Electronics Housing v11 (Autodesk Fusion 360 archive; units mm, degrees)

design "Electronics Housing" references "OLED", "LRS-35-12", "PBC"
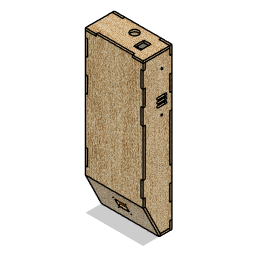
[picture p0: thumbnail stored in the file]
named bodies: "Floor", "front", "Back", "Top", "Display Pannel", "Left Side", "Right side"

design "PBC"
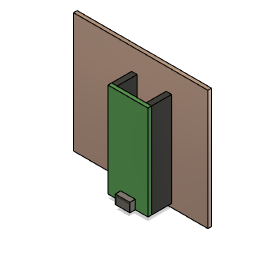
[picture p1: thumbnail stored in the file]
sketch "Sketch1" plane through (0, 0, 0) normal (0, 0, 1) x axis (1, 0, 0)
  line L1 (74, 0) -> (0, 0)
  line L2 (74, 66) -> (74, 0)
  line L3 (0, 66) -> (74, 66)
  line L4 (0, 0) -> (0, 66)
  point P1 (0, 0)
  point P2 (0, 0)
  point P3 (74, 0)
  point P4 (74, 66)
  point P5 (0, 66)
  horizontal L1
  vertical L2
  horizontal L3
  vertical L4
  coincident P1 P2
  dimension "d1" distance P3 P4 = 66
  dimension "d2" distance P4 P5 = 74
extrude "Extrude1" new body sketch "Sketch1" along normal blind 2
sketch "Sketch2" plane through (0, 0, 2) normal (0, 0, 1) x axis (1, 0, 0)
  line L1 (0, 0) -> (0, 66)
  line L2 (74, 0) -> (0, 0)
  line L3 (74, 66) -> (74, 0)
  line L4 (0, 66) -> (74, 66)
  line L5 (54, 54) -> (51, 54)
  line L6 (54, 2) -> (54, 54)
  line L7 (51, 2) -> (54, 2)
  line L8 (51, 54) -> (51, 2)
  line L9 (35, 54) -> (32, 54)
  line L10 (35, 2) -> (35, 54)
  line L11 (32, 2) -> (35, 2)
  line L12 (32, 54) -> (32, 2)
  point P10 (32, 54)
  point P11 (35, 54)
  point P12 (35, 2)
  point P7 (54, 54)
  point P8 (54, 2)
  horizontal L5
  vertical L6
  horizontal L7
  vertical L8
  horizontal L9
  vertical L10
  horizontal L11
  vertical L12
  dimension "d5" distance L3 L6 = 20
  dimension "d6" distance L6 L8 = 3
  dimension "d7" distance P10 P11 = 3
  dimension "d8" distance L6 L12 = 22
  dimension "d9" distance P10 P12 = 52
  dimension "d10" distance P7 P8 = 52
  dimension "d11" distance L4 P10 = 12
  dimension "d12" distance L4 L5 = 12
extrude "Extrude2" new body sketch "Sketch2" profile of L5 L6 L7 L8 L9 L10 L11 L12 along normal blind 11
work_plane "WorkPlane1" AlongDistance 0
sketch "Sketch3" plane through (0, 0, 13) normal (0, 0, 1) x axis (1, 0, 0)
  line L1 (32, 2) -> (32, 54)
  line L2 (54, 54) -> (54, 2)
  line L3 (54, 54) -> (32, 54)
  line L4 (54, 2) -> (54, 54)
  line L5 (32, 2) -> (54, 2)
  line L6 (32, 54) -> (32, 2)
  point P4 (54, 2)
  point P8 (54, 2)
  point P2 (32, 54)
  point P6 (32, 54)
  horizontal L3
  vertical L4
  horizontal L5
  vertical L6
  coincident P4 P8
  coincident P2 P6
extrude "Extrude3" new body sketch "Sketch3" along normal blind 2
sketch "Sketch4" plane through (0, 0, 15) normal (0, 0, 1) x axis (1, 0, 0)
  line L1 (54, 2) -> (32, 2)
  line L2 (54, 54) -> (54, 2)
  line L3 (32, 54) -> (54, 54)
  line L4 (32, 2) -> (32, 54)
  line L5 (43, 54) -> (43, 2)
  line L6 (47, 2) -> (39, 2)
  line L7 (47, 7) -> (47, 2)
  line L8 (39, 7) -> (47, 7)
  line L9 (39, 2) -> (39, 7)
  point P6 (43, 2)
  point P7 (43, 54)
  point P8 (39, 2)
  point P11 (39, 7)
  point P10 (47, 7)
  midpoint L1 P6
  midpoint L3 P7
  horizontal L6
  vertical L7
  horizontal L8
  vertical L9
  coincident L1 P8
  symmetric L5 L7 L9
  dimension "d18" distance P8 P11 = 5
  dimension "d19" distance P10 P11 = 8
extrude "Extrude4" new body sketch "Sketch4" profile of L1 L5 L6 L7 L8 L9 along normal blind 3
sketch "Sketch5" plane through (0, 2, 0) normal (0, -1, 0) x axis (1, 0, 0)
  line L1 (47, 15) -> (39, 15)
  line L2 (47, 18) -> (47, 15)
  line L3 (39, 18) -> (47, 18)
  line L4 (39, 15) -> (39, 18)
  line L5 (45.5, 17.2106) -> (40.5, 17.2106)
  line L6 (45.5, 16.6106) -> (45.5, 17.2106)
  line L7 (40.5, 16.6106) -> (45.5, 16.6106)
  line L8 (40.5, 17.2106) -> (40.5, 16.6106)
  line L9 (43, 15) -> (43, 18)
  line L10 (46.5833, 17.6974) -> (39.4167, 17.6974)
  line L11 (46.5833, 15.3264) -> (46.5833, 17.6974)
  line L12 (39.4167, 15.3264) -> (46.5833, 15.3264)
  line L13 (39.4167, 17.6974) -> (39.4167, 15.3264)
  point P10 (43, 18)
  point P11 (43, 15)
  point P6 (40.5, 17.2106)
  point P7 (45.5, 17.2106)
  horizontal L5
  vertical L6
  horizontal L7
  vertical L8
  midpoint L3 P10
  midpoint L1 P11
  symmetric L6 L8 L9
  horizontal L10
  vertical L11
  horizontal L12
  vertical L13
  symmetric L9 L11 L13
  dimension "d22" distance L5 L7 = 0.6
  dimension "d23" distance P6 P7 = 5
  dimension "d24" distance L1 L7 = 1.6106
  dimension "d25" distance L1 L12 = 0.3264
  dimension "d26" distance L4 L13 = 0.4167
  dimension "d27" distance L10 L12 = 2.371
extrude "Extrude5" cut sketch "Sketch5" profile of L5 L6 L7 L8 L9 L10 L11 L12 L13 against normal blind 4
sketch "Sketch6" plane through (0, 0, 0) normal (0, 1, 0) x axis (1, 0, 0)

design "OLED"
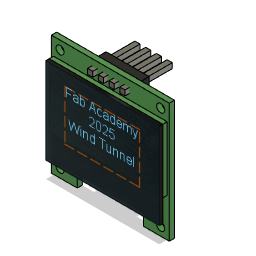
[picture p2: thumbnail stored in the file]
sketch "Sketch1" plane through (0, 0, 0) normal (0, 0, 1) x axis (1, 0, 0)
  line L1 (-13.7, 13.9) -> (13.7, 13.9)
  line L2 (-13.7, -13.9) -> (-13.7, 13.9)
  line L3 (13.7, 13.9) -> (13.7, -13.9)
  line L4 (-13.7, -13.9) -> (13.7, 13.9)
  line L5 (13.7, -13.9) -> (-13.7, 13.9)
  line L6 (13.7, 0) -> (-13.7, 0)
  line L7 (-7.7, -11.9) -> (-7.7, -13.9)
  line L8 (6.7, -10.9) -> (-6.7, -10.9)
  line L9 (7.7, -13.9) -> (7.7, -11.9)
  line L10 (-7.7, -13.9) -> (-13.7, -13.9)
  line L11 (13.7, -13.9) -> (7.7, -13.9)
  circle C1 centre (-11.7, 11.9) radius 0.95
  circle C2 centre (11.7, 11.9) radius 0.95
  circle C3 centre (-11.7, -11.9) radius 0.95
  circle C4 centre (11.7, -11.9) radius 0.95
  arc A1 centre (-6.7, -11.9) radius 1 clockwise from (-7.7, -11.9) to (-6.7, -10.9)
  arc A2 centre (6.7, -11.9) radius 1 clockwise from (6.7, -10.9) to (7.7, -11.9)
  point P6 (0, 0)
  point P1 (0, 0)
  point P9 (-13.7, 0)
  point P10 (13.7, 0)
  point P14 (7.7, -13.9)
  point P3 (-13.7, 13.9)
  point P4 (-13.7, -13.9)
  point P2 (13.7, 13.9)
  point P7 (-11.7, 11.9)
  point P8 (11.7, 11.9)
  horizontal L1
  perpendicular L1 L2
  parallel L1 L10
  parallel L2 L3
  coincident L4 P6
  coincident L5 P6
  coincident P1 P6
  midpoint L2 P9
  midpoint L3 P10
  symmetric C1 L6 C3
  symmetric C2 L6 C4
  perpendicular L7 L10
  perpendicular L7 L8
  coincident P14 L10
  perpendicular L9 L10
  tangent L7 A1
  tangent L8 A1
  tangent L8 A2
  tangent L9 A2
  equal A1 A2
  collinear L10 L11
  dimension "d1" distance P3 P4 = 27.8
  dimension "d2" distance P2 P3 = 27.4
  dimension "d3" diameter C1 = 1.9
  dimension "d4" distance L1 P7 = 2
  dimension "d5" distance L2 P7 = 2
  dimension "d6" diameter C2 = 1.9
  dimension "d7" distance L1 P8 = 2
  dimension "d8" distance L3 P8 = 2
  dimension "d17" radius A1 = 1
  dimension "d18" distance L2 L7 = 6
  dimension "d19" distance L3 L9 = 6
  dimension "d20" distance L8 L10 = 3
extrude "Extrude1" new body sketch "Sketch1" profile of L1 L2 L11 L3 C1 C2 C3 C4 along normal blind 1.2
sketch "Sketch2" plane through (0, 0, 1.2) normal (0, 0, 1) x axis (1, 0, 0)
  line L1 (13.7, 13.9) -> (13.7, -13.9)
  line L2 (-13.7, 13.9) -> (13.7, 13.9)
  line L3 (-13.7, -13.9) -> (-13.7, 13.9)
  line L4 (13.7, -13.9) -> (7.7, -13.9)
  line L5 (13.2, 9.9) -> (-13.2, 9.9)
  line L6 (13.2, -4.9) -> (13.2, 9.9)
  line L7 (-13.2, -4.9) -> (13.2, -4.9)
  line L8 (-13.2, 9.9) -> (-13.2, -4.9)
  line L9 (7.7, -13.9) -> (7.7, -11.9)
  line L10 (-7.7, -13.9) -> (-13.7, -13.9)
  line L11 (-7.7, -11.9) -> (-7.7, -13.9)
  line L12 (6.7, -10.9) -> (-6.7, -10.9)
  circle C1 centre (11.7, -11.9) radius 0.95
  circle C2 centre (-11.7, -11.9) radius 0.95
  circle C3 centre (-11.7, 11.9) radius 0.95
  circle C4 centre (11.7, 11.9) radius 0.95
  arc A1 centre (-6.7, -11.9) radius 1 clockwise from (-7.7, -11.9) to (-6.7, -10.9)
  arc A2 centre (6.7, -11.9) radius 1 clockwise from (6.7, -10.9) to (7.7, -11.9)
  horizontal L5
  vertical L6
  horizontal L7
  vertical L8
  dimension "d11" distance L2 L5 = 4
  dimension "d12" distance L4 L7 = 9
  dimension "d13" distance L3 L8 = 0.5
  dimension "d14" distance L1 L6 = 0.5
extrude "Extrude2" add sketch "Sketch2" + "Sketch3" profile of S1:L5 S1:L6 S1:L7 S1:L8 blind 1
sketch "Sketch3" plane through (0, 0, 2.2) normal (0, 0, 1) x axis (1, 0, 0)
  line L1 (13.2, -4.9) -> (-13.2, -4.9)
  line L2 (13.2, 9.9) -> (13.2, -4.9)
  line L3 (-13.2, 9.9) -> (13.2, 9.9)
  line L4 (-13.2, -4.9) -> (-13.2, 9.9)
  line L5 (13.2, 9.9) -> (-13.2, 9.9)
  line L6 (13.2, -10.1) -> (13.2, 9.9)
  line L7 (-13.2, -10.1) -> (13.2, -10.1)
  line L8 (-13.2, 9.9) -> (-13.2, -10.1)
  point P5 (-13.2, 9.9)
  point P6 (-13.2, 9.9)
  point P7 (13.2, 9.9)
  point P8 (13.2, -10.1)
  horizontal L5
  vertical L6
  horizontal L7
  vertical L8
  coincident P5 P6
  dimension "d21" distance P7 P8 = 20
  dimension "d22" distance L6 L8 = 26.4
extrude "Extrude3" new body sketch "Sketch3" along normal blind 0.8
sketch "Sketch4" plane through (0, 0, 0) normal (0, 0, -1) x axis (-1, 0, 0)
  line L1 (-7.7, -11.9) -> (-7.7, -13.9)
  line L2 (6.7, -10.9) -> (-6.7, -10.9)
  line L3 (7.7, -13.9) -> (7.7, -11.9)
  line L4 (13.7, -13.9) -> (7.7, -13.9)
  line L5 (13.7, 13.9) -> (13.7, -13.9)
  line L6 (-13.7, 13.9) -> (13.7, 13.9)
  line L7 (-13.7, -13.9) -> (-13.7, 13.9)
  line L8 (-7.7, -13.9) -> (-13.7, -13.9)
  line L9 (5, 12.9) -> (-5, 12.9)
  line L10 (5, 10.7) -> (5, 12.9)
  line L11 (-5, 10.7) -> (5, 10.7)
  line L12 (-5, 12.9) -> (-5, 10.7)
  line L13 (0, -10.9) -> (0, 13.9)
  circle C1 centre (-11.7, -11.9) radius 0.95
  circle C2 centre (-11.7, 11.9) radius 0.95
  circle C3 centre (11.7, -11.9) radius 0.95
  circle C4 centre (11.7, 11.9) radius 0.95
  arc A1 centre (-6.7, -11.9) radius 1 clockwise from (-7.7, -11.9) to (-6.7, -10.9)
  arc A2 centre (6.7, -11.9) radius 1 clockwise from (6.7, -10.9) to (7.7, -11.9)
  point P22 (0, 13.9)
  point P23 (0, -10.9)
  point P20 (5, 10.7)
  point P21 (-5, 10.7)
  point P18 (-5, 12.9)
  horizontal L9
  vertical L10
  horizontal L11
  vertical L12
  midpoint L6 P22
  midpoint L2 P23
  dimension "d25" distance P20 P21 = 10
  dimension "d26" distance L6 L9 = 1
  dimension "d27" distance P18 P21 = 2.2
extrude "Extrude4" new body sketch "Sketch4" profile of L9 L10 L11 L12 along normal blind 2.8
sketch "Sketch5" plane through (0, 0, -2.8) normal (0, 0, -1) x axis (-1, 0, 0)
  line L1 (5, 10.7) -> (-5, 10.7)
  line L2 (5, 12.9) -> (5, 10.7)
  line L3 (-5, 12.9) -> (5, 12.9)
  line L4 (-5, 10.7) -> (-5, 12.9)
  line L5 (5, 11.8) -> (-5, 11.8)
  line L6 (-3.2, 12.4) -> (-4.4, 12.4)
  line L7 (-3.2, 11.2) -> (-3.2, 12.4)
  line L8 (-4.4, 11.2) -> (-3.2, 11.2)
  line L9 (-4.4, 12.4) -> (-4.4, 11.2)
  line L10 (-0.7, 11.2) -> (-0.7, 12.4)
  line L11 (-0.7, 12.4) -> (-1.9, 12.4)
  line L12 (-1.9, 12.4) -> (-1.9, 11.2)
  line L13 (-1.9, 11.2) -> (-0.7, 11.2)
  line L14 (1.8, 11.2) -> (1.8, 12.4)
  line L15 (1.8, 12.4) -> (0.6, 12.4)
  line L16 (0.6, 12.4) -> (0.6, 11.2)
  line L17 (0.6, 11.2) -> (1.8, 11.2)
  line L18 (4.3, 11.2) -> (4.3, 12.4)
  line L19 (4.3, 12.4) -> (3.1, 12.4)
  line L20 (3.1, 12.4) -> (3.1, 11.2)
  line L21 (3.1, 11.2) -> (4.3, 11.2)
  point P6 (-5, 11.8)
  point P7 (5, 11.8)
  point P8 (-4.4, 12.4)
  point P9 (-3.2, 12.4)
  point P10 (-3.2, 11.2)
  midpoint L4 P6
  midpoint L2 P7
  horizontal L6
  vertical L7
  horizontal L8
  vertical L9
  symmetric L5 L6 L8
  dimension "d30" distance P8 P9 = 1.2
  dimension "d31" distance P9 P10 = 1.2
  dimension "d32" distance L4 L9 = 0.6
  dimension "d35" R-Pattern1-uDistance = 7.5
  dimension "d36" R-Pattern1-vDistance = 0
extrude "Extrude5" new body sketch "Sketch5" profile of L6 L7 L8 L9 L10 L11 L12 L13 L14 L15 L16 L17 L18 L19 L20 L21 along normal blind 6 and against normal blind 5
sketch "Sketch6" plane through (0, 0, 3) normal (0, 0, 1) x axis (1, 0, 0)
  dimension "d41" = 2

design "LRS-35-12"
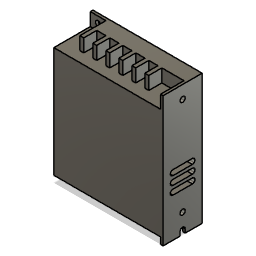
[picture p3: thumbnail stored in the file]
sketch "Sketch1" plane through (0, 0, 0) normal (0, 0, 1) x axis (1, 0, 0)
  line L1 (2, 0) -> (0, 0)
  line L2 (2, 100) -> (2, 0)
  line L3 (0, 100) -> (2, 100)
  line L4 (0, 0) -> (0, 100)
  point P1 (0, 0)
  point P2 (0, 0)
  point P3 (2, 0)
  point P5 (0, 100)
  horizontal L1
  vertical L2
  horizontal L3
  vertical L4
  coincident P1 P2
  dimension "d1" distance P2 P3 = 2
  dimension "d2" distance P2 P5 = 100
extrude "Extrude1" new body sketch "Sketch1" along normal blind 30
sketch "Sketch2" plane through (0, 0, 0) normal (0, 0, 1) x axis (1, 0, 0)
  line L1 (-82, 0) -> (0, 0)
  line L2 (-82, 100) -> (-82, 0)
  line L3 (0, 100) -> (-82, 100)
  line L4 (0, 0) -> (0, 100)
  point P1 (0, 0)
  point P2 (0, 0)
  point P5 (0, 100)
  point P3 (-82, 0)
  horizontal L1
  vertical L2
  horizontal L3
  vertical L4
  coincident P1 P2
  dimension "d5" distance P2 P5 = 100
  dimension "d6" distance P2 P3 = 82
extrude "Extrude2" add sketch "Sketch2" along normal blind 2
sketch "Sketch3" plane through (0, 0, 2) normal (0, 0, 1) x axis (1, 0, 0)
  line L1 (-82, 100) -> (0, 100)
  line L2 (-82, 0) -> (-82, 100)
  line L3 (0, 0) -> (-82, 0)
  line L4 (0, 100) -> (0, 0)
  line L5 (-82, 5) -> (0, 5)
  line L6 (-82, 90) -> (-82, 5)
  line L7 (0, 90) -> (-82, 90)
  line L8 (0, 5) -> (0, 90)
  point P6 (0, 5)
  point P8 (-82, 90)
  horizontal L5
  vertical L6
  horizontal L7
  vertical L8
  coincident L4 P6
  coincident L2 P8
  dimension "d9" distance L3 L5 = 5
  dimension "d10" distance L1 L7 = 10
extrude "Extrude3" add sketch "Sketch3" profile of L2 L4 L5 L6 L7 L8 along normal blind 28
sketch "Sketch4" plane through (0, 0, 2) normal (0, 0, 1) x axis (1, 0, 0)
  line L1 (0, 90) -> (-82, 90)
  line L2 (0, 100) -> (0, 90)
  line L3 (-82, 100) -> (0, 100)
  line L4 (-82, 90) -> (-82, 100)
  line L5 (0, 100) -> (-70, 100)
  line L6 (0, 90) -> (0, 100)
  line L7 (-70, 90) -> (0, 90)
  line L8 (-70, 100) -> (-70, 90)
  point P3 (0, 90)
  point P8 (0, 90)
  point P6 (-70, 100)
  point P7 (0, 100)
  horizontal L5
  vertical L6
  horizontal L7
  vertical L8
  coincident P3 P8
  coincident L3 P6
  dimension "d13" distance P6 P7 = 70
extrude "Extrude4" add sketch "Sketch4" profile of L1 L2 L3 L5 L6 L7 L8 along normal blind 20
sketch "Sketch5" plane through (0, 0, 22) normal (0, 0, 1) x axis (1, 0, 0)
  line L1 (0, 90) -> (-70, 90)
  line L2 (0, 100) -> (0, 90)
  line L3 (-70, 100) -> (0, 100)
  line L4 (-70, 90) -> (-70, 100)
  line L5 (-60, 100) -> (-67, 100)
  line L6 (-60, 90) -> (-60, 100)
  line L7 (-67, 90) -> (-60, 90)
  line L8 (-67, 100) -> (-67, 90)
  line L9 (-17, 103.9191) -> (-17, 90)
  line L10 (-57, 100) -> (-57, 90)
  line L11 (-50, 100) -> (-57, 100)
  line L12 (-50, 90) -> (-50, 100)
  line L13 (-57, 90) -> (-50, 90)
  line L14 (-47, 100) -> (-47, 90)
  line L15 (-40, 100) -> (-47, 100)
  line L16 (-40, 90) -> (-40, 100)
  line L17 (-47, 90) -> (-40, 90)
  line L18 (-37, 100) -> (-37, 90)
  line L19 (-30, 100) -> (-37, 100)
  line L20 (-30, 90) -> (-30, 100)
  line L21 (-37, 90) -> (-30, 90)
  line L22 (-27, 100) -> (-27, 90)
  line L23 (-20, 100) -> (-27, 100)
  line L24 (-20, 90) -> (-20, 100)
  line L25 (-27, 90) -> (-20, 90)
  line L26 (0, 100) -> (-17, 100)
  line L27 (0, 90) -> (0, 100)
  line L28 (-17, 90) -> (0, 90)
  line L29 (-17, 100) -> (-17, 90)
  point P8 (-60, 90)
  point P6 (-67, 100)
  point P10 (-17, 90)
  point P3 (0, 90)
  point P30 (0, 90)
  point P28 (-17, 100)
  point P7 (-60, 100)
  horizontal L5
  vertical L6
  horizontal L7
  vertical L8
  coincident L1 P8
  coincident L3 P6
  coincident L1 P10
  perpendicular L3 L9
  horizontal L26
  vertical L27
  horizontal L28
  vertical L29
  coincident P3 P30
  coincident L9 P28
  coincident L3 P28
  dimension "d16" distance L4 L8 = 3
  dimension "d17" distance P6 P7 = 7
  dimension "d18" distance P6 L9 = 50
  dimension "d21" R-Pattern1-uDistance = 40
  dimension "d22" R-Pattern1-vDistance = 0
extrude "Extrude5" cut sketch "Sketch5" profile of L1 L2 L3 L5 L6 L7 L8 L10 L11 L12 L13 L14 L15 L16 L17 L18 L19 L20 L21 L22 L23 L24 L25 L26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 against normal blind 10
sketch "Sketch6" plane through (0, 0, 2) normal (0, 0, 1) x axis (1, 0, 0)
  line L1 (-70, 100) -> (-70, 90)
  line L2 (-82, 100) -> (-70, 100)
  line L3 (-82, 90) -> (-82, 100)
  line L4 (-70, 90) -> (-82, 90)
  circle C1 centre (-76, 95) radius 2
  point P6 (-76, 95)
  dimension "d25" diameter C1 = 4
  dimension "d26" distance L2 P6 = 5
  dimension "d27" distance L3 P6 = 6
extrude "Extrude6" cut sketch "Sketch6" profile of C1 against normal blind 9
sketch "Sketch7" plane through (2, 0, 0) normal (1, 0, 0) x axis (0, 0, -1)
  line L1 (0, 100) -> (0, 0)
  line L2 (-30, 100) -> (0, 100)
  line L3 (-30, 0) -> (-30, 100)
  line L4 (0, 0) -> (-30, 0)
  line L5 (-15, 100) -> (-15, 0)
  line L6 (-13, 3) -> (-13, 0)
  line L7 (-17, 0) -> (-17, 3)
  line L8 (-15, 3) -> (-15, -3)
  line L9 (-13, 0) -> (-17, 0)
  arc A1 centre (-15, 3) radius 2 clockwise from (-17, 3) to (-13, 3)
  point P6 (-15, 0)
  point P7 (-15, 100)
  point P11 (-15, 3)
  point P12 (-15, 0)
  midpoint L4 P6
  midpoint L2 P7
  tangent L6 A1
  tangent A1 L7
  parallel L6 L7
  coincident L5 P11
  parallel L5 L8
  coincident P6 P12
  midpoint L8 P12
  dimension "d30" distance P11 P12 = 3
  dimension "d31" diameter A1 = 4
extrude "Extrude7" cut sketch "Sketch7" profile of L4 L6 A1 L7 L9 against normal blind 2
sketch "Sketch8" plane through (2, 0, 0) normal (1, 0, 0) x axis (0, 0, -1)
  line L1 (-17, 3) -> (-17, 0)
  line L2 (-13, 0) -> (-13, 3)
  line L3 (0, 0) -> (-13, 0)
  line L4 (0, 100) -> (0, 0)
  line L5 (-30, 100) -> (0, 100)
  line L6 (-30, 0) -> (-30, 100)
  line L7 (-17, 0) -> (-30, 0)
  line L8 (-15, 100) -> (-15, 5)
  line L9 (-22.5, 34) -> (-7.5, 34)
  line L10 (-7.5, 30) -> (-22.5, 30)
  line L11 (-22.5, 32) -> (-7.5, 32)
  line L12 (-22.5, 40.5) -> (-7.5, 40.5)
  line L13 (-7.5, 36.5) -> (-22.5, 36.5)
  line L14 (-22.5, 47) -> (-7.5, 47)
  line L15 (-7.5, 43) -> (-22.5, 43)
  arc A1 centre (-15, 3) radius 2 clockwise from (-17, 3) to (-13, 3)
  circle C1 centre (-15, 15) radius 2
  circle C2 centre (-15, 90) radius 2
  arc A2 centre (-22.5, 32) radius 2 clockwise from (-22.5, 30) to (-22.5, 34)
  arc A3 centre (-7.5, 32) radius 2 clockwise from (-7.5, 34) to (-7.5, 30)
  arc A4 centre (-22.5, 38.5) radius 2 clockwise from (-22.5, 36.5) to (-22.5, 40.5)
  arc A5 centre (-7.5, 38.5) radius 2 clockwise from (-7.5, 40.5) to (-7.5, 36.5)
  arc A6 centre (-22.5, 45) radius 2 clockwise from (-22.5, 43) to (-22.5, 47)
  arc A7 centre (-7.5, 45) radius 2 clockwise from (-7.5, 47) to (-7.5, 43)
  point P11 (-15, 5)
  point P12 (-15, 100)
  point P13 (-15, 15)
  point P14 (-15, 90)
  point P21 (-15, 32)
  point P2 (-17, 0)
  midpoint A1 P11
  midpoint L5 P12
  coincident L8 P13
  coincident L8 P14
  tangent L9 A2
  tangent A2 L10
  parallel L9 L10
  tangent L10 A3
  tangent L9 A3
  perpendicular L8 L11
  coincident L8 P21
  midpoint L11 P21
  dimension "d34" diameter C1 = 4
  dimension "d35" diameter C2 = 4
  dimension "d36" distance L7 P13 = 15
  dimension "d37" distance L5 P14 = 10
  dimension "d38" diameter A2 = 4
  dimension "d39" distance P2 P21 = 32
  dimension "d42" R-Pattern1-uDistance = 0
  dimension "d43" R-Pattern1-vDistance = 13
extrude "Extrude8" cut sketch "Sketch8" profile of A1 C1 C2 L9 A2 L10 A3 L12 A4 L13 A5 L14 A6 L15 A7 against normal blind 4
